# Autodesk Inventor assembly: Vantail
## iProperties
Shininess: 64.0
Length Units: 11269
Angle Units: 11279
Time Units: 11290
Mass Units: 11283
Length Display Precision: 3
Angle Display Precision: 2
Compacted: True
Created: 2007-01
Part Number: Vantail
Document SubType Name: Assembly
Designer: plantier
Density: 0.0
Volumn: 0.0
Area: 0.0
PropertySet Name: Model Information
Control State: 0
Master: False
Checked Out: False
Author: plantier
